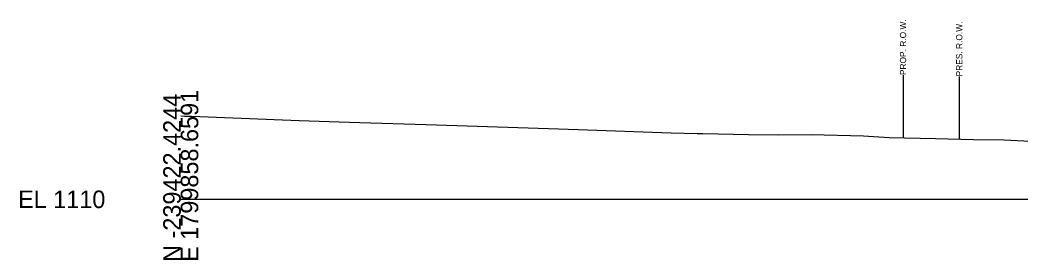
# Model space of a CAD drawing. Extents: x 214513 to 217151, y 214739 to 216780.
# Drawn here: x 214722.7 to 214882.7, y 215738.7 to 215777 of the extents above; entities that cross this region are included whole.
import ezdxf

# ---------------------------------------------------------------- set-up
doc = ezdxf.new("R2010")
doc.units = 0
for name, color, linetype in [('DESIGN - ROW - Right-of-Way Linework', 7, 'Continuous'), ('DESIGN - TRANSPORTATION - Text', 7, 'Continuous'), ('Section', 7, 'Continuous'), ('SURVEY - DTM GRAPHICS - Triangles', 7, 'Continuous'), ('SURVEY - PROPERTY - ROW Lines', 7, 'Continuous'), ('XSCell', 7, 'Continuous')]:
    doc.layers.add(name, color=color, linetype=linetype)

msp = doc.modelspace()

# ---------------------------------------------------------------- linework, layer by layer
at = {"layer": 'DESIGN - ROW - Right-of-Way Linework'}
msp.add_lwpolyline([(214863.8, 215768.2), (214863.8, 215758.2)], dxfattribs=at)
at = {"layer": 'SURVEY - DTM GRAPHICS - Triangles'}
msp.add_lwpolyline([(214748.36, 215761.68), (214748.98, 215761.66), (214749.1, 215761.65), (214750.07, 215761.62), (214767.29, 215760.96), (214773.67, 215760.75), (214776.97, 215760.65), (214787.56, 215760.32), (214792.5, 215760.16), (214807.16, 215759.65), (214811.88, 215759.5), (214826.74, 215758.97), (214830.88, 215758.89), (214831.82, 215758.87), (214839.11, 215758.73), (214843.82, 215758.67), (214849.11, 215758.69), (214857.5, 215758.52), (214861.58, 215758.26), (214868.98, 215758.08), (214875.06, 215757.94), (214879.94, 215757.86), (214884.17, 215757.64)], dxfattribs=at)
at = {"layer": 'SURVEY - PROPERTY - ROW Lines'}
msp.add_lwpolyline([(214872.79, 215767.99), (214872.79, 215757.99)], dxfattribs=at)
at = {"layer": 'XSCell'}
msp.add_line((214748.36, 215748.36), (214898.36, 215748.36), dxfattribs=at)

# ---------------------------------------------------------------- texts
at = {"layer": 'DESIGN - TRANSPORTATION - Text'}
for s, p in [('PROP. R.O.W.', (214864.3, 215768.2)), ('PRES. R.O.W.', (214873.29, 215767.99))]:
    msp.add_text(s, height=1, rotation=90, dxfattribs=at).set_placement(p)
at = {"layer": 'Section'}
msp.add_text('-', height=0.0001, dxfattribs=at).set_placement((214748.36, 215748.36))
at = {"layer": 'XSCell'}
for s, p in [('N -239422.4244', (214748.36, 215738.36)), ('E 1799858.6591', (214751.16, 215738.36))]:
    msp.add_text(s, height=2.8, rotation=90, dxfattribs=at).set_placement(p)
msp.add_text('EL 1110', height=2.8, dxfattribs=at).set_placement((214722.36, 215746.96))

doc.saveas('drawing.dxf')
